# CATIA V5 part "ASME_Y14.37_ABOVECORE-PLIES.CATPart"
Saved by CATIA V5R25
Part number: ASME_Y14.37_ABOVECORE_PLIES-303
Material "Honeycomb": density 40 kg/m3
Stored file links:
  \\NW\Data\MSE-Composites\STEP Interoperability\ExampleData\ASME_Y14.37 Test Parts\ASSEMBLY VERSION\ASME_Y14.37_ABOVECORE-PLIES.CATPart
  C:\Users\jvl2147\Desktop\CompositesCatalog.CATMaterial
  \\Nw\787lib\787-PROCINT-WKG\Dom_SSDBS\DM\!!ShareFileForWritingServices\Composites\Standards and References\ASMEY-14.37\ASMEY-14.37_COMPOSITES.CATMaterial
  C:\Program Files\Dassault Systemes\B25SP2PRALL\win_b64\startup\materials\honeycomb.jpg
  \\Nw\787lib\787-PROCINT-WKG\Dom_SSDBS\DM\!!ShareFileForWritingServices\Composites\Standards and References\ASME Y14.37\PLY TABEL_-1 BOND ASSEMBLY.xlsx
  \\Nw\787lib\787-PROCINT-WKG\Dom_SSDBS\DM\!!ShareFileForWritingServices\Composites\Standards and References\ASME Y14.37\ASME_Y14.37_VALIDATION-PROPERTIES_CORE STIFFENED BOND PART.xlsx.xlsx
  Copy (2) of CA_ASME_Y14.37_CORE-STIFFENED-BOND-PART.CATPart
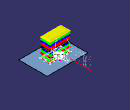
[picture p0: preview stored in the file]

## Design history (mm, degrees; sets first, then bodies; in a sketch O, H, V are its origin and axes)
Parameters
  StandardPlyThickness = 0.254 mm
  `Scale Value` = 100
CompParametersFeature1 "CATCoParametersFeatName": Value 0, Value 45, Value -45, Value 90, Orientations 999.999, Orientations 90
CompStacking1 "Stacking"
CompReviewTools1 "Review tools"
f4a2d38f3ddc11d3a929006094b99c4b_11 "CATTPSSet"
TTRSSet1
Toolside_View1 "CATTPSView"
Set1 "CONSTRUCTION (REF)"
  Sketch1 on XY plane of AxisSystem2, origin (0, 0, 0), H (1, 0, 0), V (0, 1, 0)
    line L1 (-1012.309, 818.5005) -> (1278.0398, 818.5005)
    line L2 (1278.0398, 818.5005) -> (1278.0398, -788.7181)
    line L3 (1278.0398, -788.7181) -> (-1012.309, -788.7181)
    line L4 (-1012.309, -788.7181) -> (-1012.309, 818.5005)
    horizontal: L1 H, L3 H
    vertical: L2 V, L4 V
  Fill1: Boundary Sketch1
  CurvePar1: Offset CompStdContourFeature1, Support Fill1, Offset2 0, Offset1 50.8
  Plane1: type Offset, RefPlane YZ plane of AxisSystem2, Offset -598
  Plane2: type Offset, RefPlane YZ plane of AxisSystem2, Offset -598, reversed
  Plane3: type Offset, RefPlane ZX plane of AxisSystem2, Offset -292
  Plane4: type Offset, RefPlane ZX plane of AxisSystem2, Offset -292, reversed
  MultiSel1
  CompStdContourFeature1 "CATCoStdContourFeatName": SupportSurface Fill1, ClosedSetOfCurves ({intersect ToIntersect1 Plane2, ToIntersect2 Fill1}; {intersect ToIntersect1 Plane3, ToIntersect2 Fill1}; {intersect ToIntersect1 Plane1, ToIntersect2 Fill1}; {intersect ToIntersect1 Plane4, ToIntersect2 Fill1}), ExtrapolDist 0.2
  Plane5: type Offset, RefPlane Plane2, Offset 254, reversed
  Intersect1: ToIntersect1 Plane5, ToIntersect2 Fill1
  Plane6: type Offset, RefPlane Plane1, Offset 254
  Intersect2: ToIntersect1 Plane6, ToIntersect2 Fill1
  Plane7: type Offset, RefPlane ZX plane of AxisSystem2, Offset -50.8
  CurvePar2: Offset CompStdContourFeature1, Offset2 0, Offset1 139.7
  Point1: (0, 0, 0), in AxisSystem2
  AxisSystem1: origin (0, 0, -127), X (1, 0, 0), Y (0, 1, 0), Z (0, 0, 1)
  Point2: (215.6851, 77.4411, 0)
  Point3: type OnCurve, Support edge [ZX plane of AxisSystem2 | YZ plane of AxisSystem2], Length 127
  Point4: type OnPlane, Support Join1, H -130.714, V 273.957, Direction (1, 0, 0)
  Split1: ToCut Circle1, Cutting {intersect ToIntersect1 Plane4, ToIntersect2 Fill1}
  Circle1: type CtrRad, Start 0, End 180, Center Point4, Support Join1, Radius 76.2, FirstDirection (1, 0, 0)
Set2 "ENGINEERING GEOMETRY"
  Join1 "TOOLSIDE SURFACE": Elements Fill1
  AxisSystem2 "PLY ORIENTATION COORDINATE SYSTEM": origin (0, 0, 0), X (1, 0, 0), Y (0, 1, 0), Z (0, 0, 1)
Set3 "EXPLODED PLIES VIEW (REF)"
  CLDGeom1 "PLY 1:10745:0"
  CLDGeom2 "PLY 2:10745:0"
  CLDGeom3 "PLY 3:10721:0"
  CLDGeom4 "PLY 4:10721:45"
  CLDGeom5 "PLY 5:10721:0"
  CLDGeom6 "PLY 6:10721:45"
  CLDGeom7 "PLY 7:10679:-45"
  DatumSurface1 "Core -103"
  CLDGeom8 "PLY 8:10679:0"
  CLDGeom9 "PLY 9:10721:0"
  CLDGeom10 "PLY 10:10721:-45"
  CLDGeom11 "PLY 11:10721:45"
  CLDGeom12 "PLY 12:10721:90"
Body1 "ASME_Y14.37_CORE_PART-101 (REF)" (main body)
  Solid1 "ASME_Y14.37_CORE_PART-101": solid without history
Body2 "CORE -103"
  CompCoreSolidFormGeometry1 "Geometry_8": Curves CurvePar1, ReferenceSurface Fill1, VariableOffsets 0, VariableSlopes 20, BasicHeight 25.4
